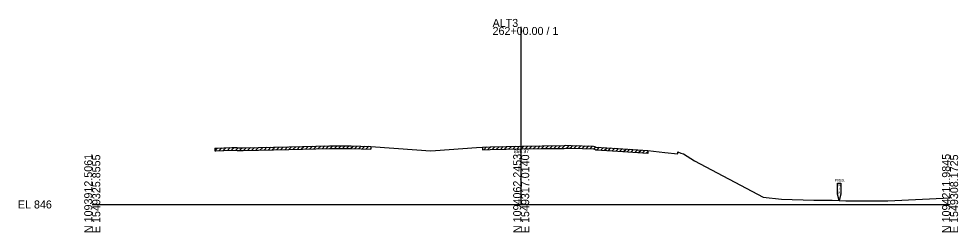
# Model space of a CAD drawing. Extents: x -26 to 1303, y -10 to 19582.
# Drawn here: x 974.3 to 1302.8, y 15490.3 to 15564.9 of the extents above; entities that cross this region are included whole.
import ezdxf

# ---------------------------------------------------------------- set-up
doc = ezdxf.new("R2010")
doc.units = 0
for name, color, linetype in [('Default', 7, 'Continuous'), ('RD_GPK_XS_Cell', 7, 'Continuous'), ('RD_XS_ExGround', 7, 'Continuous'), ('RD_XS_ExPaveRet', 7, 'Continuous'), ('RD_XS_ExRW', 7, 'Continuous'), ('RD_XS_TX_Elev_EX', 7, 'Continuous')]:
    doc.layers.add(name, color=color, linetype=linetype)

msp = doc.modelspace()

# ---------------------------------------------------------------- linework, layer by layer
at = {"layer": 'RD_GPK_XS_Cell'}
for p, q in [((1150, 15500), (1150, 15562.06)), ((1000, 15500), (1150, 15500)), ((1150, 15500), (1300, 15500))]:
    msp.add_line(p, q, dxfattribs=at)
at = {"layer": 'RD_XS_ExGround'}
msp.add_lwpolyline([(1042.88, 15519.7), (1043.27, 15519.71), (1048.77, 15519.91), (1050.64, 15519.86), (1051.31, 15519.83), (1052.07, 15519.82), (1052.8, 15519.82), (1068.69, 15520.13), (1083.02, 15520.5), (1090.51, 15520.46), (1097.43, 15520.32), (1113.56, 15519.13), (1118.32, 15518.74), (1120.03, 15518.88), (1134.32, 15519.91), (1136.53, 15520.09), (1139.13, 15520.13), (1150.29, 15520.37), (1157.36, 15520.47), (1165.08, 15520.56), (1165.6, 15520.69), (1167.49, 15520.64), (1175.34, 15520.4), (1175.78, 15520.23), (1176.16, 15520.09), (1183.8, 15519.6), (1194.33, 15518.84), (1200.23, 15518.11), (1204.75, 15517.7), (1204.77, 15518.36), (1205.87, 15517.97), (1206.81, 15517.67), (1210.64, 15515.23), (1234.67, 15502.53), (1241.07, 15501.86), (1252.37, 15501.48), (1258.75, 15501.48), (1263.51, 15501.29), (1278.26, 15501.28), (1300, 15502.36)], dxfattribs=at)
at = {"layer": 'RD_XS_ExPaveRet'}
for p, q in [((1047.25, 15518.91), (1048.24, 15519.89)), ((1048.72, 15518.96), (1049.65, 15519.89)), ((1055.76, 15518.93), (1056.73, 15519.9)), ((1057.2, 15518.96), (1058.17, 15519.93)), ((1058.65, 15518.99), (1059.61, 15519.95)), ((1060.09, 15519.01), (1061.06, 15519.98)), ((1061.53, 15519.04), (1062.5, 15520.01)), ((1062.97, 15519.07), (1063.94, 15520.04)), ((1064.41, 15519.1), (1065.38, 15520.07)), ((1065.85, 15519.12), (1066.82, 15520.09)), ((1067.3, 15519.15), (1068.26, 15520.12)), ((1068.74, 15519.18), (1069.71, 15520.16)), ((1070.19, 15519.22), (1071.17, 15520.19)), ((1071.64, 15519.26), (1072.62, 15520.23)), ((1073.09, 15519.29), (1074.07, 15520.27)), ((1074.55, 15519.33), (1075.52, 15520.31)), ((1076, 15519.37), (1076.97, 15520.34)), ((1077.45, 15519.41), (1078.42, 15520.38)), ((1078.9, 15519.44), (1079.88, 15520.42)), ((1080.35, 15519.48), (1081.33, 15520.46)), ((1081.8, 15519.52), (1082.78, 15520.49)), ((1083.25, 15519.55), (1084.19, 15520.49)), ((1084.66, 15519.54), (1085.6, 15520.49)), ((1086.06, 15519.53), (1087.01, 15520.48)), ((1087.47, 15519.53), (1088.41, 15520.47)), ((1088.88, 15519.52), (1089.82, 15520.46)), ((1090.28, 15519.51), (1091.22, 15520.44)), ((1091.67, 15519.49), (1092.6, 15520.42)), ((1093.06, 15519.46), (1093.99, 15520.39)), ((1094.45, 15519.43), (1095.38, 15520.36)), ((1095.83, 15519.4), (1096.76, 15520.33)), ((1097.43, 15520.32), (1097.43, 15519.32)), ((1136.53, 15520.09), (1136.53, 15519.09)), ((1136.95, 15519.15), (1137.92, 15520.11)), ((1138.39, 15519.17), (1139.36, 15520.14)), ((1139.83, 15519.2), (1140.8, 15520.17)), ((1141.28, 15519.23), (1142.25, 15520.2)), ((1142.72, 15519.26), (1143.69, 15520.23)), ((1144.17, 15519.29), (1145.14, 15520.26)), ((1145.61, 15519.32), (1146.58, 15520.29)), ((1147.06, 15519.36), (1148.03, 15520.33)), ((1148.5, 15519.39), (1149.47, 15520.36)), ((1149.95, 15519.42), (1150.91, 15520.38)), ((1151.38, 15519.44), (1152.35, 15520.4)), ((1152.82, 15519.46), (1153.78, 15520.42)), ((1154.25, 15519.48), (1155.22, 15520.44)), ((1155.69, 15519.5), (1156.65, 15520.46)), ((1157.12, 15519.52), (1158.08, 15520.48)), ((1158.55, 15519.54), (1159.51, 15520.5)), ((1159.98, 15519.55), (1160.94, 15520.51)), ((1161.41, 15519.57), (1162.37, 15520.53)), ((1162.84, 15519.58), (1163.8, 15520.54)), ((1164.27, 15519.6), (1165.28, 15520.61)), ((1165.82, 15519.73), (1166.74, 15520.66)), ((1167.2, 15519.7), (1168.12, 15520.62)), ((1168.57, 15519.65), (1169.49, 15520.58)), ((1169.94, 15519.61), (1170.86, 15520.53)), ((1171.31, 15519.57), (1172.24, 15520.49)), ((1172.69, 15519.53), (1173.61, 15520.45)), ((1174.06, 15519.49), (1174.98, 15520.41)), ((1175.41, 15519.42), (1176.1, 15520.11)), ((1176.52, 15519.12), (1177.41, 15520.01)), ((1177.85, 15519.03), (1178.74, 15519.92)), ((1042.88, 15518.78), (1043.83, 15519.73)), ((1042.88, 15519.7), (1042.88, 15518.7)), ((1044.32, 15518.8), (1045.3, 15519.78)), ((1045.78, 15518.85), (1046.77, 15519.84)), ((1050.1, 15518.92), (1051.02, 15519.84)), ((1051.47, 15518.88), (1052.41, 15519.82)), ((1052.88, 15518.88), (1053.85, 15519.84)), ((1054.32, 15518.9), (1055.29, 15519.87)), ((1097.22, 15519.38), (1097.43, 15519.59)), ((1179.17, 15518.95), (1180.07, 15519.84)), ((1180.5, 15518.86), (1181.4, 15519.75)), ((1181.83, 15518.77), (1182.72, 15519.67)), ((1183.16, 15518.69), (1184.05, 15519.58)), ((1184.48, 15518.6), (1185.37, 15519.49)), ((1185.8, 15518.5), (1186.69, 15519.39)), ((1187.12, 15518.41), (1188.01, 15519.3)), ((1188.44, 15518.32), (1189.33, 15519.2)), ((1189.76, 15518.22), (1190.65, 15519.11)), ((1191.08, 15518.13), (1191.97, 15519.01)), ((1192.4, 15518.03), (1193.29, 15518.92)), ((1193.72, 15517.94), (1194.33, 15518.55)), ((1194.33, 15518.84), (1194.33, 15517.84))]:
    msp.add_line(p, q, dxfattribs=at)
for points in [[(1042.88, 15518.75), (1043.27, 15518.76), (1048.77, 15518.96), (1050.64, 15518.91), (1051.31, 15518.88), (1052.07, 15518.87), (1052.8, 15518.87), (1068.69, 15519.18), (1083.02, 15519.55), (1090.51, 15519.51), (1097.43, 15519.37)], [(1136.53, 15519.14), (1139.13, 15519.18), (1150.29, 15519.42), (1157.36, 15519.52), (1165.08, 15519.61), (1165.6, 15519.74), (1167.49, 15519.69), (1175.34, 15519.45), (1175.78, 15519.28), (1176.16, 15519.14), (1183.8, 15518.65), (1194.33, 15517.89)]]:
    msp.add_lwpolyline(points, dxfattribs=at)
at = {"layer": 'RD_XS_ExRW'}
msp.add_lwpolyline([(1260.66, 15507.4), (1261.76, 15507.4), (1261.76, 15503.57), (1261.21, 15501.38), (1260.66, 15503.57)], close=True, dxfattribs=at)

# ---------------------------------------------------------------- texts
at = {"layer": 'Default'}
msp.add_text('-', height=0.0001, dxfattribs=at).set_placement((1000, 15500))
at = {"layer": 'RD_GPK_XS_Cell'}
for s, p in [('ALT3', (1140, 15562.06)), ('262+00.00 / 1', (1140, 15559.26)), ('EL 846', (974, 15498.6))]:
    msp.add_text(s, height=2.8, dxfattribs=at).set_placement(p)
for s, p in [('N 1093912.5061', (1000, 15490)), ('E 1549325.8555', (1002.8, 15490)), ('N 1094062.2453', (1150, 15490)), ('E 1549317.0140', (1152.8, 15490)), ('N 1094211.9845', (1300, 15490)), ('E 1549308.1725', (1302.8, 15490))]:
    msp.add_text(s, height=2.8, rotation=90, dxfattribs=at).set_placement(p)
at = {"layer": 'RD_XS_ExRW'}
for s, p in [('PRES.', (1259.66, 15508.02)), ('R', (1260.92, 15506.3)), ('W', (1260.74, 15503.68)), ('/', (1261.05, 15504.99))]:
    msp.add_text(s, height=0.875, dxfattribs=at).set_placement(p)
at = {"layer": 'RD_XS_TX_Elev_EX'}
msp.add_text('866.37', height=1.25, dxfattribs=at).set_placement((1147.45, 15517.94))

doc.saveas('drawing.dxf')
